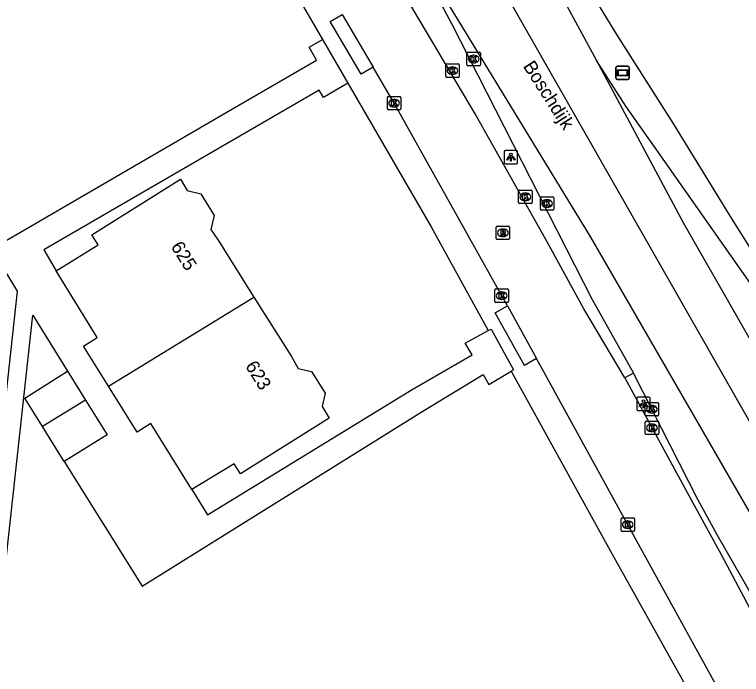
# Model space of a CAD drawing. Extents: x 158132 to 159658, y 385257 to 387209.
# Drawn here: x 159568.6 to 159622.7, y 385917.2 to 385966.3 of the extents above; entities that cross this region are included whole.
import ezdxf

# ---------------------------------------------------------------- set-up
doc = ezdxf.new("R2010")
doc.units = 0
for name, color, linetype in [('IMGEO_Kolk', 7, 'Continuous'), ('IMGEO_Lichtpunt', 7, 'Continuous'), ('IMGEO_Openbare_ruimte_label', 7, 'Continuous'), ('IMGEO_Pand', 7, 'Continuous'), ('IMGEO_Pand_nummerreeks', 7, 'Continuous'), ('IMGEO_Reclamebord', 7, 'Continuous'), ('IMGEO_Rijbaan_lokaal_open', 7, 'Continuous'), ('IMGEO_Rijbaan_regionaal_gesloten', 7, 'Continuous'), ('IMGEO_Rioolput', 7, 'Continuous'), ('IMGEO_Verkeerseiland_groen', 7, 'Continuous'), ('IMGEO_Voetpad_open', 7, 'Continuous')]:
    doc.layers.add(name, color=color, linetype=linetype)

msp = doc.modelspace()

# ---------------------------------------------------------------- linework, layer by layer
at = {"layer": 'IMGEO_Kolk'}
for p, q in [((159602.306, 385962.54), (159602.306, 385963.392)), ((159602.381, 385963.466), (159603.233, 385963.466)), ((159602.794, 385963.246), (159602.819, 385963.246)), ((159603.307, 385963.392), (159603.307, 385962.54)), ((159600.723, 385961.674), (159600.723, 385962.526)), ((159600.798, 385962.6), (159601.65, 385962.6)), ((159601.724, 385962.526), (159601.724, 385961.674)), ((159602.817, 385962.686), (159602.792, 385962.686)), ((159601.211, 385962.38), (159601.236, 385962.38)), ((159603.233, 385962.466), (159602.381, 385962.466)), ((159601.65, 385961.6), (159600.798, 385961.6)), ((159601.234, 385961.82), (159601.209, 385961.82)), ((159596.379, 385959.261), (159596.379, 385960.113)), ((159596.454, 385960.187), (159597.306, 385960.187)), ((159596.867, 385959.967), (159596.892, 385959.967)), ((159597.38, 385960.113), (159597.38, 385959.261)), ((159596.89, 385959.407), (159596.865, 385959.407)), ((159597.306, 385959.187), (159596.454, 385959.187)), ((159606.148, 385952.278), (159606.148, 385953.13)), ((159606.223, 385953.204), (159607.075, 385953.204)), ((159606.636, 385952.984), (159606.661, 385952.984)), ((159607.149, 385953.13), (159607.149, 385952.278)), ((159606.659, 385952.424), (159606.634, 385952.424)), ((159607.766, 385951.784), (159607.766, 385952.636)), ((159607.841, 385952.71), (159608.693, 385952.71)), ((159608.254, 385952.49), (159608.279, 385952.49)), ((159608.767, 385952.636), (159608.767, 385951.784)), ((159607.075, 385952.204), (159606.223, 385952.204)), ((159608.693, 385951.71), (159607.841, 385951.71)), ((159608.277, 385951.93), (159608.252, 385951.93)), ((159604.388, 385944.927), (159604.388, 385945.779)), ((159604.463, 385945.853), (159605.315, 385945.853)), ((159605.389, 385945.779), (159605.389, 385944.927)), ((159604.876, 385945.633), (159604.901, 385945.633)), ((159605.315, 385944.853), (159604.463, 385944.853)), ((159604.899, 385945.073), (159604.874, 385945.073)), ((159615.569, 385936.47), (159615.569, 385937.322)), ((159615.644, 385937.396), (159616.496, 385937.396)), ((159616.057, 385937.176), (159616.082, 385937.176)), ((159616.57, 385937.322), (159616.57, 385936.47)), ((159616.08, 385936.616), (159616.055, 385936.616)), ((159616.496, 385936.396), (159615.644, 385936.396)), ((159615.648, 385936.013), (159616.5, 385936.013)), ((159615.573, 385935.087), (159615.573, 385935.939)), ((159616.061, 385935.793), (159616.086, 385935.793)), ((159616.574, 385935.939), (159616.574, 385935.087)), ((159616.5, 385935.013), (159615.648, 385935.013)), ((159616.084, 385935.233), (159616.059, 385935.233)), ((159613.773, 385927.883), (159613.773, 385928.735)), ((159613.848, 385928.809), (159614.7, 385928.809)), ((159614.261, 385928.589), (159614.286, 385928.589)), ((159614.774, 385928.735), (159614.774, 385927.883)), ((159614.284, 385928.029), (159614.259, 385928.029)), ((159614.7, 385927.809), (159613.848, 385927.809))]:
    msp.add_line(p, q, dxfattribs=at)
for points in [[(159602.306, 385962.54), (159602.306, 385963.392)], [(159602.381, 385963.466), (159603.233, 385963.466)], [(159602.627, 385963.166), (159602.75, 385963.166), (159602.75, 385963.015), (159602.88, 385963.166), (159603.044, 385963.166), (159602.898, 385963.015), (159603.051, 385962.766), (159602.899, 385962.766), (159602.814, 385962.93), (159602.75, 385962.863), (159602.75, 385962.766), (159602.627, 385962.766), (159602.627, 385963.166)], [(159603.307, 385963.392), (159603.307, 385962.54)], [(159600.723, 385961.674), (159600.723, 385962.526)], [(159600.798, 385962.6), (159601.65, 385962.6)], [(159601.724, 385962.526), (159601.724, 385961.674)], [(159601.044, 385962.3), (159601.167, 385962.3), (159601.167, 385962.149), (159601.297, 385962.3), (159601.461, 385962.3), (159601.315, 385962.149), (159601.468, 385961.9), (159601.316, 385961.9), (159601.231, 385962.064), (159601.167, 385961.997), (159601.167, 385961.9), (159601.044, 385961.9), (159601.044, 385962.3)], [(159603.233, 385962.466), (159602.381, 385962.466)], [(159601.65, 385961.6), (159600.798, 385961.6)], [(159596.379, 385959.261), (159596.379, 385960.113)], [(159596.454, 385960.187), (159597.306, 385960.187)], [(159596.7, 385959.887), (159596.823, 385959.887), (159596.823, 385959.736), (159596.953, 385959.887), (159597.117, 385959.887), (159596.971, 385959.736), (159597.124, 385959.487), (159596.972, 385959.487), (159596.887, 385959.651), (159596.823, 385959.584), (159596.823, 385959.487), (159596.7, 385959.487), (159596.7, 385959.887)], [(159597.38, 385960.113), (159597.38, 385959.261)], [(159597.306, 385959.187), (159596.454, 385959.187)], [(159606.148, 385952.278), (159606.148, 385953.13)], [(159606.223, 385953.204), (159607.075, 385953.204)], [(159606.469, 385952.904), (159606.592, 385952.904), (159606.592, 385952.753), (159606.722, 385952.904), (159606.886, 385952.904), (159606.74, 385952.753), (159606.893, 385952.504), (159606.741, 385952.504), (159606.656, 385952.668), (159606.592, 385952.601), (159606.592, 385952.504), (159606.469, 385952.504), (159606.469, 385952.904)], [(159607.149, 385953.13), (159607.149, 385952.278)], [(159607.766, 385951.784), (159607.766, 385952.636)], [(159607.841, 385952.71), (159608.693, 385952.71)], [(159608.087, 385952.41), (159608.21, 385952.41), (159608.21, 385952.259), (159608.34, 385952.41), (159608.504, 385952.41), (159608.358, 385952.259), (159608.511, 385952.01), (159608.359, 385952.01), (159608.274, 385952.174), (159608.21, 385952.107), (159608.21, 385952.01), (159608.087, 385952.01), (159608.087, 385952.41)], [(159608.767, 385952.636), (159608.767, 385951.784)], [(159607.075, 385952.204), (159606.223, 385952.204)], [(159608.693, 385951.71), (159607.841, 385951.71)], [(159604.388, 385944.927), (159604.388, 385945.779)], [(159604.463, 385945.853), (159605.315, 385945.853)], [(159605.389, 385945.779), (159605.389, 385944.927)], [(159604.709, 385945.553), (159604.832, 385945.553), (159604.832, 385945.402), (159604.962, 385945.553), (159605.126, 385945.553), (159604.98, 385945.402), (159605.133, 385945.153), (159604.981, 385945.153), (159604.896, 385945.317), (159604.832, 385945.25), (159604.832, 385945.153), (159604.709, 385945.153), (159604.709, 385945.553)], [(159605.315, 385944.853), (159604.463, 385944.853)], [(159615.569, 385936.47), (159615.569, 385937.322)], [(159615.644, 385937.396), (159616.496, 385937.396)], [(159615.89, 385937.096), (159616.013, 385937.096), (159616.013, 385936.945), (159616.143, 385937.096), (159616.307, 385937.096), (159616.161, 385936.945), (159616.314, 385936.696), (159616.162, 385936.696), (159616.077, 385936.86), (159616.013, 385936.793), (159616.013, 385936.696), (159615.89, 385936.696), (159615.89, 385937.096)], [(159616.57, 385937.322), (159616.57, 385936.47)], [(159616.496, 385936.396), (159615.644, 385936.396)], [(159615.648, 385936.013), (159616.5, 385936.013)], [(159615.573, 385935.087), (159615.573, 385935.939)], [(159615.894, 385935.713), (159616.017, 385935.713), (159616.017, 385935.562), (159616.147, 385935.713), (159616.311, 385935.713), (159616.165, 385935.562), (159616.318, 385935.313), (159616.166, 385935.313), (159616.081, 385935.477), (159616.017, 385935.41), (159616.017, 385935.313), (159615.894, 385935.313), (159615.894, 385935.713)], [(159616.574, 385935.939), (159616.574, 385935.087)], [(159616.5, 385935.013), (159615.648, 385935.013)], [(159613.773, 385927.883), (159613.773, 385928.735)], [(159613.848, 385928.809), (159614.7, 385928.809)], [(159614.094, 385928.509), (159614.217, 385928.509), (159614.217, 385928.358), (159614.347, 385928.509), (159614.511, 385928.509), (159614.365, 385928.358), (159614.518, 385928.109), (159614.366, 385928.109), (159614.281, 385928.273), (159614.217, 385928.206), (159614.217, 385928.109), (159614.094, 385928.109), (159614.094, 385928.509)], [(159614.774, 385928.735), (159614.774, 385927.883)], [(159614.7, 385927.809), (159613.848, 385927.809)]]:
    msp.add_lwpolyline(points, dxfattribs=at)
for centre, start, end in [((159602.383, 385963.39), 91.552, 178.448), ((159602.383, 385963.39), 91.552, 178.448), ((159603.231, 385963.39), 1.552, 88.448), ((159603.231, 385963.39), 1.552, 88.448), ((159600.8, 385962.524), 91.552, 178.448), ((159600.8, 385962.524), 91.552, 178.448), ((159601.648, 385962.524), 1.552, 88.448), ((159601.648, 385962.524), 1.552, 88.448), ((159602.383, 385962.542), 181.552, 268.448), ((159602.383, 385962.542), 181.552, 268.448), ((159603.231, 385962.542), 271.552, 358.448), ((159603.231, 385962.542), 271.552, 358.448), ((159600.8, 385961.676), 181.552, 268.448), ((159600.8, 385961.676), 181.552, 268.448), ((159601.648, 385961.676), 271.552, 358.448), ((159601.648, 385961.676), 271.552, 358.448), ((159596.456, 385960.111), 91.552, 178.448), ((159596.456, 385960.111), 91.552, 178.448), ((159597.304, 385960.111), 1.552, 88.448), ((159597.304, 385960.111), 1.552, 88.448), ((159596.456, 385959.263), 181.552, 268.448), ((159596.456, 385959.263), 181.552, 268.448), ((159597.304, 385959.263), 271.552, 358.448), ((159597.304, 385959.263), 271.552, 358.448), ((159606.225, 385953.128), 91.552, 178.448), ((159606.225, 385953.128), 91.552, 178.448), ((159607.073, 385953.128), 1.552, 88.448), ((159607.073, 385953.128), 1.552, 88.448), ((159606.225, 385952.28), 181.552, 268.448), ((159606.225, 385952.28), 181.552, 268.448), ((159607.073, 385952.28), 271.552, 358.448), ((159607.073, 385952.28), 271.552, 358.448), ((159607.843, 385952.634), 91.552, 178.448), ((159607.843, 385952.634), 91.552, 178.448), ((159608.691, 385952.634), 1.552, 88.448), ((159608.691, 385952.634), 1.552, 88.448), ((159607.843, 385951.786), 181.552, 268.448), ((159607.843, 385951.786), 181.552, 268.448), ((159608.691, 385951.786), 271.552, 358.448), ((159608.691, 385951.786), 271.552, 358.448), ((159604.465, 385945.777), 91.552, 178.448), ((159604.465, 385945.777), 91.552, 178.448), ((159605.313, 385945.777), 1.552, 88.448), ((159605.313, 385945.777), 1.552, 88.448), ((159604.465, 385944.929), 181.552, 268.448), ((159604.465, 385944.929), 181.552, 268.448), ((159605.313, 385944.929), 271.552, 358.448), ((159605.313, 385944.929), 271.552, 358.448), ((159615.646, 385937.32), 91.552, 178.448), ((159615.646, 385937.32), 91.552, 178.448), ((159616.494, 385937.32), 1.552, 88.448), ((159616.494, 385937.32), 1.552, 88.448), ((159615.646, 385936.472), 181.552, 268.448), ((159615.646, 385936.472), 181.552, 268.448), ((159615.65, 385935.937), 91.552, 178.448), ((159615.65, 385935.937), 91.552, 178.448), ((159616.494, 385936.472), 271.552, 358.448), ((159616.494, 385936.472), 271.552, 358.448), ((159616.498, 385935.937), 1.552, 88.448), ((159616.498, 385935.937), 1.552, 88.448), ((159615.65, 385935.089), 181.552, 268.448), ((159615.65, 385935.089), 181.552, 268.448), ((159616.498, 385935.089), 271.552, 358.448), ((159616.498, 385935.089), 271.552, 358.448), ((159613.85, 385928.733), 91.552, 178.448), ((159613.85, 385928.733), 91.552, 178.448), ((159614.698, 385928.733), 1.552, 88.448), ((159614.698, 385928.733), 1.552, 88.448), ((159613.85, 385927.885), 181.552, 268.448), ((159613.85, 385927.885), 181.552, 268.448), ((159614.698, 385927.885), 271.552, 358.448), ((159614.698, 385927.885), 271.552, 358.448)]:
    msp.add_arc(centre, 0.0765, start, end, dxfattribs=at)
for centre, major_axis, ratio, start_param, end_param in [((159602.793, 385962.966), (-0.387, 0.002), 0.722429, 4.712389, 7.853982), ((159602.818, 385962.966), (-0.39, 0.002), 0.717154, 1.570796, 4.712389), ((159601.21, 385962.1), (-0.387, 0.002), 0.722429, 4.712389, 7.853982), ((159601.235, 385962.1), (-0.39, 0.002), 0.717154, 1.570796, 4.712389), ((159596.866, 385959.687), (-0.387, 0.002), 0.722429, 4.712389, 7.853982), ((159596.891, 385959.687), (-0.39, 0.002), 0.717154, 1.570796, 4.712389), ((159606.635, 385952.704), (-0.387, 0.002), 0.722429, 4.712389, 7.853982), ((159606.66, 385952.704), (-0.39, 0.002), 0.717154, 1.570796, 4.712389), ((159608.253, 385952.21), (-0.387, 0.002), 0.722429, 4.712389, 7.853982), ((159608.278, 385952.21), (-0.39, 0.002), 0.717154, 1.570796, 4.712389), ((159604.875, 385945.353), (-0.387, 0.002), 0.722429, 4.712389, 7.853982), ((159604.9, 385945.353), (-0.39, 0.002), 0.717154, 1.570796, 4.712389), ((159616.056, 385936.896), (-0.387, 0.002), 0.722429, 4.712389, 7.853982), ((159616.081, 385936.896), (-0.39, 0.002), 0.717154, 1.570796, 4.712389), ((159616.06, 385935.513), (-0.387, 0.002), 0.722429, 4.712389, 7.853982), ((159616.085, 385935.513), (-0.39, 0.002), 0.717154, 1.570796, 4.712389), ((159614.26, 385928.309), (-0.387, 0.002), 0.722429, 4.712389, 7.853982), ((159614.285, 385928.309), (-0.39, 0.002), 0.717154, 1.570796, 4.712389)]:
    msp.add_ellipse(centre, major_axis=major_axis, ratio=ratio, start_param=start_param, end_param=end_param, dxfattribs=at)
at = {"layer": 'IMGEO_Lichtpunt'}
for p, q in [((159605.081, 385956.07), (159605.081, 385955.263)), ((159605.081, 385956.07), (159605.081, 385955.263)), ((159605.983, 385956.165), (159605.175, 385956.165)), ((159605.983, 385956.165), (159605.175, 385956.165)), ((159606.077, 385955.263), (159606.077, 385956.07)), ((159606.077, 385955.263), (159606.077, 385956.07)), ((159605.175, 385955.169), (159605.983, 385955.169)), ((159605.175, 385955.169), (159605.983, 385955.169)), ((159614.938, 385937.697), (159614.938, 385936.89)), ((159614.938, 385937.697), (159614.938, 385936.89)), ((159615.84, 385937.792), (159615.032, 385937.792)), ((159615.84, 385937.792), (159615.032, 385937.792)), ((159615.934, 385936.89), (159615.934, 385937.697)), ((159615.934, 385936.89), (159615.934, 385937.697)), ((159615.032, 385936.796), (159615.84, 385936.796)), ((159615.032, 385936.796), (159615.84, 385936.796))]:
    msp.add_line(p, q, dxfattribs=at)
for points in [[(159605.455, 385955.734), (159605.494, 385955.706), (159605.306, 385955.444), (159605.268, 385955.471), (159605.455, 385955.734)], [(159605.557, 385955.686), (159605.604, 385955.686), (159605.604, 385955.364), (159605.557, 385955.364), (159605.557, 385955.686)], [(159605.667, 385955.706), (159605.705, 385955.733), (159605.892, 385955.471), (159605.853, 385955.443), (159605.667, 385955.706)], [(159615.312, 385937.361), (159615.351, 385937.333), (159615.163, 385937.071), (159615.125, 385937.098), (159615.312, 385937.361)], [(159615.414, 385937.313), (159615.461, 385937.313), (159615.461, 385936.991), (159615.414, 385936.991), (159615.414, 385937.313)], [(159615.524, 385937.333), (159615.562, 385937.36), (159615.749, 385937.098), (159615.71, 385937.07), (159615.524, 385937.333)]]:
    msp.add_lwpolyline(points, dxfattribs=at)
for centre in [(159605.58, 385955.868), (159615.437, 385937.495)]:
    msp.add_circle(centre, 0.0994, dxfattribs=at)
for centre, start, end in [((159605.175, 385956.07), 90, 180), ((159605.175, 385956.07), 90, 180), ((159605.983, 385956.07), 0, 90), ((159605.983, 385956.07), 0, 90), ((159605.175, 385955.263), 180, 270), ((159605.175, 385955.263), 180, 270), ((159605.983, 385955.263), 270, 0), ((159605.983, 385955.263), 270, 360), ((159615.032, 385937.697), 90, 180), ((159615.032, 385937.697), 90, 180), ((159615.84, 385937.697), 0, 90), ((159615.84, 385937.697), 0, 90), ((159615.032, 385936.89), 180, 270), ((159615.032, 385936.89), 180, 270), ((159615.84, 385936.89), 270, 0), ((159615.84, 385936.89), 270, 360)]:
    msp.add_arc(centre, 0.0946, start, end, dxfattribs=at)
at = {"layer": 'IMGEO_Pand'}
for points in [[(159571.73, 385947.196), (159574.852, 385949.125), (159574.379, 385949.891), (159580.975, 385954.016), (159581.491, 385953.191), (159582.502, 385952.937), (159583.497, 385951.309), (159583.252, 385950.282), (159583.789, 385949.474), (159586.449, 385945.253)], [(159575.615, 385938.615), (159573.752, 385941.601), (159574.787, 385942.247), (159571.73, 385947.196)], [(159575.615, 385938.615), (159586.449, 385945.253)], [(159586.449, 385945.253), (159589.236, 385940.832), (159589.747, 385939.942), (159590.737, 385939.699), (159591.741, 385938.097), (159591.535, 385937.094), (159592.051, 385936.239), (159585.46, 385932.081), (159584.978, 385932.841), (159581.834, 385930.927)], [(159570.708, 385935.608), (159569.385, 385937.734), (159572.576, 385939.724)], [(159572.576, 385939.724), (159573.915, 385937.573)], [(159581.834, 385930.927), (159578.781, 385935.847), (159577.746, 385935.2), (159575.615, 385938.615)], [(159573.915, 385937.573), (159570.708, 385935.608)], [(159573.915, 385937.573), (159575.521, 385934.992), (159572.33, 385933.002)], [(159572.33, 385933.002), (159570.708, 385935.608)]]:
    msp.add_lwpolyline(points, dxfattribs=at)
at = {"layer": 'IMGEO_Reclamebord'}
for p, q in [((159613.394, 385961.537), (159613.394, 385962.337)), ((159613.394, 385962.337), (159613.394, 385961.537)), ((159613.494, 385962.437), (159614.284, 385962.437)), ((159614.284, 385962.437), (159613.494, 385962.437)), ((159614.384, 385962.337), (159614.384, 385961.537)), ((159614.384, 385961.537), (159614.384, 385962.337)), ((159614.284, 385961.437), (159613.494, 385961.437)), ((159613.494, 385961.437), (159614.284, 385961.437))]:
    msp.add_line(p, q, dxfattribs=at)
for points in [[(159613.495, 385962.169), (159614.283, 385962.169), (159614.283, 385961.705), (159613.495, 385961.705), (159613.495, 385962.169)], [(159613.56, 385962.104), (159613.56, 385961.77), (159614.218, 385961.77), (159614.218, 385962.104), (159613.56, 385962.104)]]:
    msp.add_lwpolyline(points, dxfattribs=at)
for centre, start, end in [((159613.494, 385962.337), 90, 180), ((159613.494, 385962.337), 90, 180), ((159614.284, 385962.337), 0, 90), ((159614.284, 385962.337), 360, 90), ((159613.494, 385961.537), 180, 270), ((159613.494, 385961.537), 180, 270), ((159614.284, 385961.537), 270, 0), ((159614.284, 385961.537), 270, 0)]:
    msp.add_arc(centre, 0.1, start, end, dxfattribs=at)
at = {"layer": 'IMGEO_Rijbaan_lokaal_open'}
for points in [[(159614.046, 385939.227), (159611.008, 385944.38), (159608.296, 385949.322), (159602.91, 385958.899), (159597.879, 385967.409), (159593.949, 385974.057), (159589.628, 385980.657), (159585.402, 385986.335), (159579.934, 385993.03), (159575.204, 385998.555)], [(159593.025, 385966.279), (159595.331, 385962.368)], [(159605.315, 385944.586), (159604.892, 385945.35), (159596.877, 385959.69), (159595.331, 385962.368)], [(159605.315, 385944.586), (159607.486, 385940.665)], [(159622.049, 385914.2), (159614.277, 385928.306), (159607.486, 385940.665)], [(159614.046, 385939.227), (159618.816, 385930.485), (159621.218, 385926.097), (159622.894, 385922.952), (159624.803, 385919.32), (159625.723, 385917.698)]]:
    msp.add_lwpolyline(points, dxfattribs=at)
at = {"layer": 'IMGEO_Rijbaan_regionaal_gesloten'}
for points in [[(159502.819, 386139.087), (159504.13, 386136.946), (159515.24, 386119.368), (159527.943, 386099.13), (159539.949, 386079.661), (159544.835, 386071.884), (159552.342, 386059.808), (159557.924, 386051.069), (159563.773, 386041.659), (159571.719, 386029.072), (159578.522, 386018.189), (159585.114, 386007.517), (159589.825, 386000), (159590.289, 385999.259), (159593.396, 385994.269), (159596.933, 385988.677), (159599.683, 385984.229), (159601.113, 385981.934), (159602.622, 385979.469), (159604.449, 385976.284), (159609.132, 385968.039), (159611.944, 385962.856)], [(159499.651, 386137.219), (159520.444, 386103.637), (159574.471, 386016.885), (159600.527, 385975.989), (159644.13, 385899.529), (159644.386, 385899.081)], [(159591.605, 386000), (159596.646, 385991.907), (159602.941, 385981.726), (159608.363, 385973.078), (159613.436, 385964.792), (159617.678, 385958.128), (159622.026, 385951.054), (159624.937, 385946.415), (159629.345, 385939.311), (159632.602, 385934.24), (159635.134, 385930.142), (159638.579, 385924.4), (159641.537, 385919.55), (159648.364, 385908.74), (159650.138, 385905.881), (159650.819, 385904.784)], [(159596.488, 385974.358), (159601.152, 385965.61), (159611.619, 385945.057), (159614.705, 385939.573)], [(159642.042, 385896.892), (159641.915, 385897.112), (159611.522, 385949.695), (159598.531, 385971.012), (159596.488, 385974.358)], [(159611.944, 385962.856), (159618.413, 385950.738), (159646.344, 385901.945), (159646.73, 385901.271)], [(159649.117, 385903.501), (159648.597, 385904.404), (159633.744, 385930.178), (159632.235, 385932.811), (159627.24, 385940.801), (159626.869, 385941.335), (159617.02, 385955.345), (159614.131, 385959.461), (159611.944, 385962.856)], [(159626.382, 385918.054), (159620.936, 385927.556), (159619.492, 385930.188), (159614.705, 385939.573)]]:
    msp.add_lwpolyline(points, dxfattribs=at)
at = {"layer": 'IMGEO_Rioolput'}
for p, q in [((159604.479, 385949.604), (159604.479, 385950.456)), ((159604.554, 385950.53), (159605.406, 385950.53)), ((159604.967, 385950.31), (159604.992, 385950.31)), ((159605.48, 385950.456), (159605.48, 385949.604)), ((159604.99, 385949.75), (159604.965, 385949.75)), ((159605.406, 385949.53), (159604.554, 385949.53))]:
    msp.add_line(p, q, dxfattribs=at)
for points in [[(159604.479, 385949.604), (159604.479, 385950.456)], [(159604.554, 385950.53), (159605.406, 385950.53)], [(159605.068, 385950.228), (159604.816, 385950.23), (159604.816, 385949.83)], [(159604.994, 385950.149), (159604.94, 385950.149), (159604.94, 385950.068)], [(159605.48, 385950.456), (159605.48, 385949.604)], [(159604.816, 385949.83), (159604.94, 385949.83), (159604.94, 385949.992), (159604.951, 385949.992)], [(159604.94, 385950.068), (159604.992, 385950.068)], [(159604.998, 385949.963), (159605.069, 385949.83), (159605.209, 385949.83), (159605.144, 385949.956)], [(159605.406, 385949.53), (159604.554, 385949.53)]]:
    msp.add_lwpolyline(points, dxfattribs=at)
for centre, radius, start, end in [((159604.556, 385950.454), 0.0765, 91.552, 178.448), ((159604.556, 385950.454), 0.0765, 91.552, 178.448), ((159605, 385950.053), 0.0964, 77.0061, 93.1865), ((159605.014, 385950.11), 0.0378, 276.6634, 79.6772), ((159605.067, 385950.118), 0.109, 350.3612, 89.416), ((159605.065, 385950.118), 0.112, 277.5842, 350.9817), ((159605.404, 385950.454), 0.0765, 1.552, 88.448), ((159605.404, 385950.454), 0.0765, 1.552, 88.448), ((159604.556, 385949.606), 0.0765, 181.552, 268.448), ((159604.556, 385949.606), 0.0765, 181.552, 268.448), ((159604.95, 385949.939), 0.0533, 26.0293, 88.6989), ((159604.976, 385950.257), 0.19, 274.7715, 282.9687), ((159605.049, 385949.903), 0.108, 29.5134, 73.7905), ((159605.404, 385949.606), 0.0765, 271.552, 358.448), ((159605.404, 385949.606), 0.0765, 271.552, 358.448)]:
    msp.add_arc(centre, radius, start, end, dxfattribs=at)
for centre, major_axis, ratio, start_param, end_param in [((159604.966, 385950.03), (-0.387, 0.002), 0.722429, 4.712389, 7.853982), ((159604.991, 385950.03), (-0.39, 0.002), 0.717154, 1.570796, 4.712389)]:
    msp.add_ellipse(centre, major_axis=major_axis, ratio=ratio, start_param=start_param, end_param=end_param, dxfattribs=at)
at = {"layer": 'IMGEO_Verkeerseiland_groen'}
msp.add_lwpolyline([(159614.705, 385939.573), (159614.046, 385939.227)], dxfattribs=at)
at = {"layer": 'IMGEO_Voetpad_open'}
for points in [[(159582.66, 385978.825), (159586.231, 385973.567), (159591.547, 385964.41)], [(159595.331, 385962.368), (159594.435, 385961.84), (159592.129, 385965.751), (159593.025, 385966.279)], [(159565.497, 385915.064), (159568.861, 385945.693), (159566.907, 385948.83), (159569.362, 385950.255), (159584.863, 385959.253), (159591.117, 385962.883), (159590.563, 385963.838), (159591.547, 385964.41)], [(159591.547, 385964.41), (159593.433, 385961.16)], [(159593.433, 385961.16), (159591.631, 385960.115), (159591.314, 385960.661), (159585.878, 385957.505), (159570.82, 385948.764), (159571.73, 385947.196)], [(159593.433, 385961.16), (159599.633, 385950.479), (159603.878, 385942.752)], [(159607.486, 385940.665), (159606.576, 385940.161), (159604.405, 385944.082), (159605.315, 385944.586)], [(159566.84, 385915.285), (159569.982, 385943.892), (159572.576, 385939.724)], [(159581.834, 385930.927), (159583.005, 385929.039), (159598.227, 385938.364), (159602.681, 385940.944), (159602.181, 385941.82), (159603.878, 385942.752)], [(159603.878, 385942.752), (159604.109, 385942.858), (159605.764, 385939.828), (159605.6, 385939.741)], [(159572.33, 385933.002), (159578.119, 385923.72), (159598.897, 385936.678), (159603.517, 385939.481), (159603.939, 385938.744), (159605.6, 385939.741)], [(159605.6, 385939.741), (159612.976, 385926.325), (159620.297, 385913.244)]]:
    msp.add_lwpolyline(points, dxfattribs=at)

# ---------------------------------------------------------------- texts
at = {"layer": 'IMGEO_Openbare_ruimte_label'}
msp.add_text('Boschdijk', height=1, rotation=302.4668, dxfattribs=at).set_placement((159606.446, 385962.438))
at = {"layer": 'IMGEO_Pand_nummerreeks'}
for s, p in [('625', (159580.231, 385949.007)), ('623', (159585.769, 385940.119))]:
    msp.add_text(s, height=1, rotation=301.9251, dxfattribs=at).set_placement(p)

doc.saveas('drawing.dxf')
